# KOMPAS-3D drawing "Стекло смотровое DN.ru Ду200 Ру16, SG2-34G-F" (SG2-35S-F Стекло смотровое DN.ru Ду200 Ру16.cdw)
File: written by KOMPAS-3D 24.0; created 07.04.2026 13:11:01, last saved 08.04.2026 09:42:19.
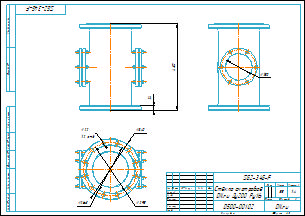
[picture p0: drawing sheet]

Document properties: Автор: Main; Форматы листов документа: A3; Полное имя файла: ..\SG2-34G-F Стекло смотровое DN.ru Ду200 Ру16\SG2-34G-F Стекло смотровое DN.ru Ду200 Ру16.m3d; Масса: 55; Наименование: Стекло смотровое DN.ru Ду200 Ру16; Количество листов документа: 1; Примечание: D500-00090

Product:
- Part/product: Стекло смотровое DN.ru Ду200 Ру16  | designation SG2-34G-F
    Масса: 55
    Раздел спецификации: Прочие изделия
    Примечание: D500-00090

Views: Вид 1, Снизу, Проекционный вид 2, Проекционный вид 3
Referenced files in D:\DN.ru Аутсерс\Стекло смотровое DN.ru\Стекло смотровое DN.ru SG2-34G-F тип В ГОСТ 21836-2021 Ду100 Ру16, углеродистая сталь, фланцевое\: SG2-34G-F тип В Стекло смотровое DN.ru Ду100 Ру16.m3d, SG2-34G-F тип ВСтекло смотровое DN.ru Ду100 Ру16.cdw
Referenced files in D:\DN.ru Аутсерс\Стекло смотровое DN.ru\SG2-34G-F Стекло смотровое DN.ru Ду200 Ру16\: SG2-34G-F Стекло смотровое DN.ru Ду200 Ру16.m3d
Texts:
  SG2-34G-F
  Стекло смотровое
  DN.ru Ду200 Ру16
  Стекло смотровое DN.ru Ду200 Ру16
  SG2-34G-F Стекло смотровое DN.ru Ду200 Ру16
Dimensions and other numbers on the sheet: 0; 3; 2; 4; 480; 24; 22; 12 отв.; 340; 295; 268; 150; 1:4; 1; 55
